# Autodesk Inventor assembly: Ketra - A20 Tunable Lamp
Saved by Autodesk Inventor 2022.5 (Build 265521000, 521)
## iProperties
Created: 2025-02
Part Number: Ketra - A20 Tunable Lamp
Document SubType Name: Assembly
Designer: AdminForWorker
Title: Ketra - A20 Tunable Lamp v4
Author: AdminForWorker
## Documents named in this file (2)
- c:\worker\convert-fusion-r06-cosv3\tmp\job-1\26\temp\files\9f389096-616c-4089-bee7-3010d11b0d58\Ketra - A20 Tunable Lamp v4.iam
- c:\worker\convert-fusion-r06-cosv3\tmp\job-1\26\temp\files\9f389096-616c-4089-bee7-3010d11b0d58\Ketra A20.ipt
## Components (1 placed, 1 different names)
1. Ketra A20:1
